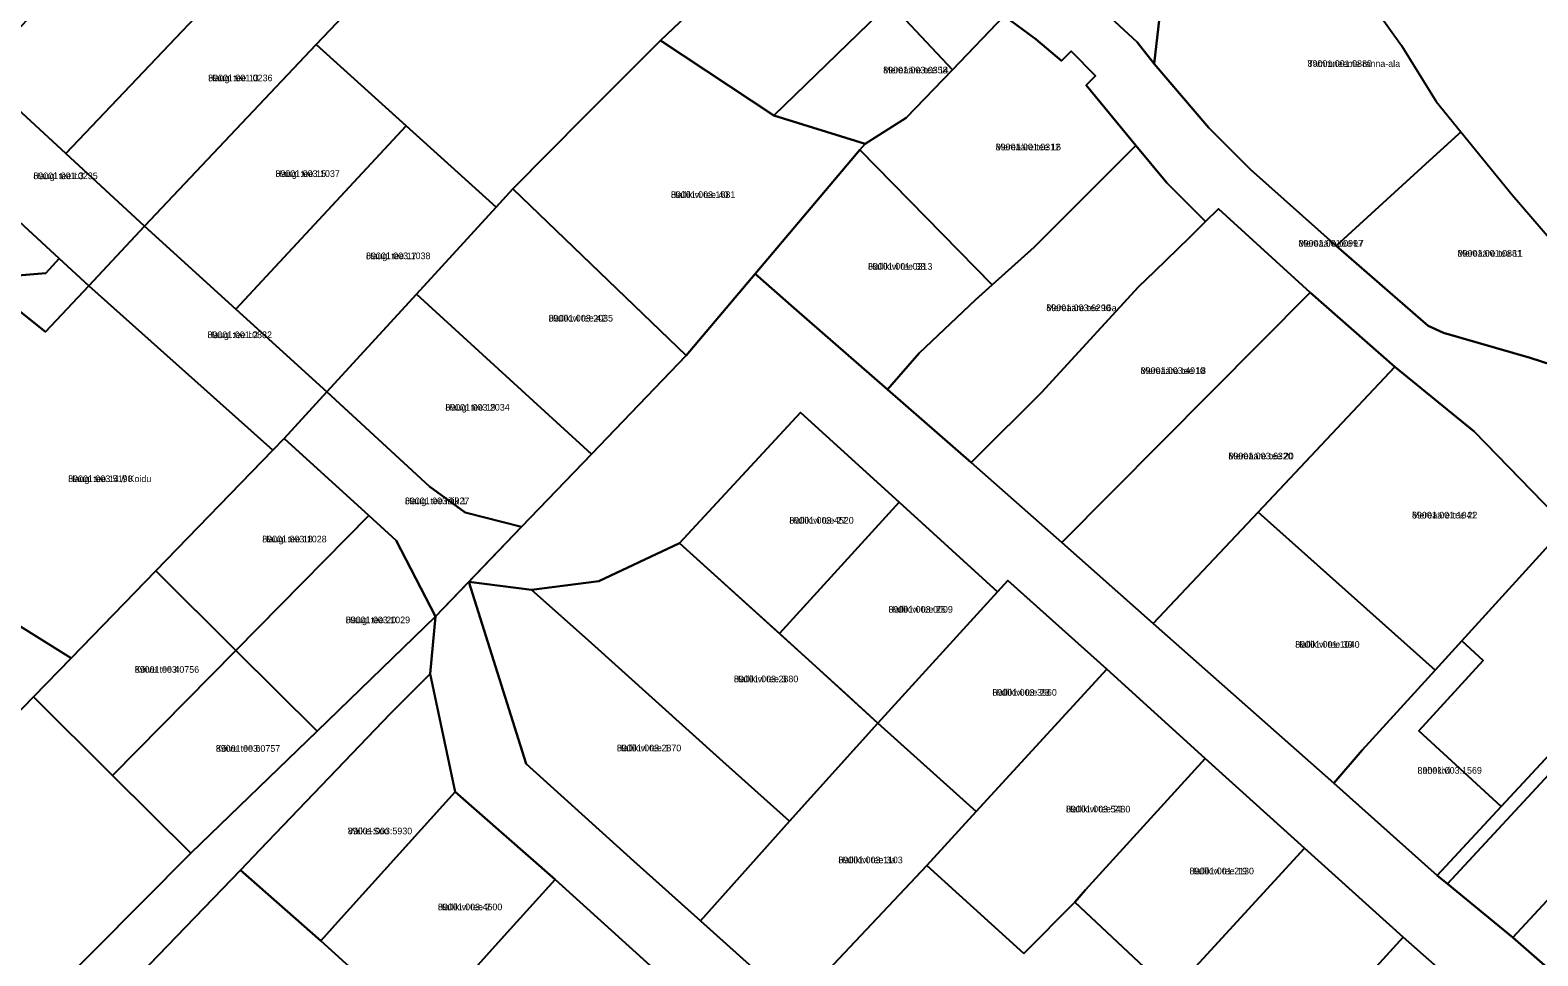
# Model space of a CAD drawing. Extents: x 526849 to 562296, y 6591741 to 6618546.
# Drawn here: x 550234.2 to 550573.7, y 6599209.9 to 6599418.5 of the extents above; entities that cross this region are included whole.
import ezdxf

# ---------------------------------------------------------------- set-up
doc = ezdxf.new("R2010")
doc.units = 0
for name, color, linetype in [('L_AADRESS', 7, 'Continuous'), ('PIIR', 7, 'Continuous'), ('TUNNUS', 7, 'Continuous')]:
    doc.layers.add(name, color=color, linetype=linetype)

msp = doc.modelspace()

# ---------------------------------------------------------------- linework, layer by layer
at = {"layer": 'PIIR'}
for points in [[(550338.48, 6599453.54), (550370.8, 6599421.44), (550391.08, 6599440.74), (550396.22, 6599451.02), (550407.35, 6599463.14), (550412.23, 6599460.02), (550417.73, 6599455.69), (550376.16, 6599416.14), (550359.05, 6599399.06), (550342.91, 6599382.73), (550339.12, 6599378.58), (550318.87, 6599396.92), (550298.56, 6599415.29), (550306.33, 6599423.38), (550319.47, 6599435.16), (550333.28, 6599447.47)], [(550376.16, 6599416.14), (550417.73, 6599455.69), (550419.39, 6599457.64), (550455.35, 6599423.66), (550453.51, 6599421.72), (550441.89, 6599409.52), (550427.82, 6599424.57), (550401.66, 6599399.22)], [(550263.02, 6599452.56), (550283, 6599433.66), (550242.17, 6599390.67), (550222.34, 6599408.94), (550243.43, 6599431.58)], [(550487.36, 6599410.9), (550489.63, 6599431.21), (550506.1, 6599445.17), (550515.6, 6599453.23), (550516.25, 6599453.78), (550522.47, 6599443.81), (550543.02, 6599415.02), (550550.88, 6599402.41), (550556.4, 6599395.59), (550555.84, 6599395.08), (550549.32, 6599389.11), (550528.35, 6599369.9), (550509.06, 6599387.08), (550499.62, 6599396.48)], [(550469.45, 6599428.95), (550464, 6599432.68), (550476.55, 6599445.78), (550480.91, 6599450.33), (550489.63, 6599431.21), (550487.36, 6599410.9), (550483.5, 6599415.75), (550475.54, 6599423.16)], [(550283, 6599433.66), (550289.09, 6599440.06), (550306.33, 6599423.38), (550298.56, 6599415.29), (550259.95, 6599374.33), (550242.17, 6599390.67)], [(550441.89, 6599409.52), (550431.44, 6599398.72), (550422.22, 6599392.9), (550401.66, 6599399.22), (550427.82, 6599424.57)], [(550441.89, 6599409.52), (550453.51, 6599421.72), (550460.67, 6599416.46), (550466.44, 6599411.56), (550468.6, 6599413.73), (550474.13, 6599408.17), (550472.01, 6599406.11), (550483.21, 6599392.49), (550460.29, 6599369.56), (550450.82, 6599361.08), (550421.04, 6599391.5), (550422.22, 6599392.9), (550431.44, 6599398.72)], [(550259.95, 6599374.33), (550298.56, 6599415.29), (550318.87, 6599396.92), (550280.5, 6599355.65)], [(550401.66, 6599399.22), (550422.22, 6599392.9), (550421.04, 6599391.5), (550397.45, 6599363.54), (550381.95, 6599345.17), (550342.91, 6599382.73), (550359.05, 6599399.06), (550376.16, 6599416.14)], [(550209.75, 6599395.56), (550222.34, 6599408.94), (550242.17, 6599390.67), (550259.95, 6599374.33), (550247.35, 6599360.87), (550240.73, 6599367)], [(550280.5, 6599355.65), (550318.87, 6599396.92), (550339.12, 6599378.58), (550321.17, 6599358.99), (550300.98, 6599336.96)], [(550189.25, 6599373.56), (550209.75, 6599395.56), (550240.73, 6599367), (550237.69, 6599363.71), (550227.81, 6599362.88), (550208.06, 6599340.59), (550181.7, 6599365.4)], [(550549.04, 6599351.83), (550528.35, 6599369.9), (550549.32, 6599389.11), (550555.84, 6599395.08), (550556.4, 6599395.59), (550567.95, 6599381.35), (550576.84, 6599371.11), (550590.97, 6599355.63), (550595.81, 6599351.02), (550596.43, 6599350.3), (550595.36, 6599349.21), (550590.01, 6599343.77), (550585.65, 6599339.33), (550579.2, 6599342.29), (550572.05, 6599344.67), (550552.5, 6599350.29)], [(550397.45, 6599363.54), (550421.04, 6599391.5), (550450.82, 6599361.08), (550447.1, 6599357.75), (550434.4, 6599345.67), (550427.23, 6599337.48), (550406.2, 6599355.88)], [(550446.09, 6599321.03), (550427.23, 6599337.48), (550434.4, 6599345.67), (550447.1, 6599357.75), (550450.82, 6599361.08), (550460.29, 6599369.56), (550483.21, 6599392.49), (550490.19, 6599384.06), (550498.86, 6599375.34), (550495.31, 6599371.79), (550487.37, 6599364.14), (550483.78, 6599360.68), (550461.95, 6599336.83), (550447.05, 6599322.05)], [(550342.91, 6599382.73), (550381.95, 6599345.17), (550360.57, 6599322.93), (550321.17, 6599358.99), (550339.12, 6599378.58)], [(550501.82, 6599378.23), (550522.44, 6599359.35), (550466.57, 6599303.05), (550446.09, 6599321.03), (550447.05, 6599322.05), (550461.95, 6599336.83), (550483.78, 6599360.68), (550487.37, 6599364.14), (550495.31, 6599371.79), (550498.86, 6599375.34)], [(550259.95, 6599374.33), (550280.5, 6599355.65), (550300.98, 6599336.96), (550291.38, 6599326.47), (550288.83, 6599323.85), (550247.35, 6599360.87)], [(550237.69, 6599363.71), (550240.73, 6599367), (550247.35, 6599360.87), (550237.63, 6599350.54), (550231.69, 6599355.25), (550210.88, 6599331.55), (550203.96, 6599323.72), (550203.55, 6599323.26), (550192.22, 6599310.51), (550196.62, 6599306.2), (550125.59, 6599231.83), (550116.88, 6599240.1), (550126.93, 6599250.64), (550129.93, 6599247.76), (550183.92, 6599304.66), (550183.9, 6599313.16), (550208.06, 6599340.59), (550227.81, 6599362.88)], [(550208.6, 6599318.8), (550203.96, 6599323.72), (550210.88, 6599331.55), (550231.69, 6599355.25), (550237.63, 6599350.54), (550247.35, 6599360.87), (550288.83, 6599323.85), (550262.46, 6599296.65), (550243.36, 6599276.95), (550196.62, 6599306.2)], [(550321.17, 6599358.99), (550360.57, 6599322.93), (550344.81, 6599306.54), (550332.11, 6599309.76), (550324.13, 6599315.66), (550300.98, 6599336.96)], [(550487.14, 6599284.76), (550466.57, 6599303.05), (550522.44, 6599359.35), (550541.54, 6599342.64), (550510.77, 6599309.88)], [(550510.77, 6599309.88), (550541.54, 6599342.64), (550559.43, 6599328.07), (550580.1, 6599306.74), (550556.65, 6599280.86), (550550.6, 6599274.25)], [(550300.98, 6599336.96), (550324.13, 6599315.66), (550332.11, 6599309.76), (550344.81, 6599306.54), (550332.95, 6599294.15), (550325.49, 6599286.38), (550316.63, 6599303.48), (550310.42, 6599309.14), (550291.38, 6599326.47)], [(550429.87, 6599312.11), (550402.92, 6599282.55), (550380.43, 6599302.85), (550407.7, 6599332.32)], [(550262.46, 6599296.65), (550288.83, 6599323.85), (550291.38, 6599326.47), (550310.42, 6599309.14), (550280.52, 6599278.71)], [(550580.1, 6599306.74), (550590.03, 6599318.17), (550614.16, 6599295.87), (550565.51, 6599243.53), (550546.92, 6599260.6), (550561.44, 6599276.48), (550556.65, 6599280.87)], [(550417.71, 6599269.08), (550402.92, 6599282.55), (550429.87, 6599312.11), (550452.04, 6599291.89), (550425.09, 6599262.33)], [(550280.52, 6599278.71), (550310.42, 6599309.14), (550316.63, 6599303.48), (550325.49, 6599286.38), (550298.78, 6599260.56)], [(550510.77, 6599309.88), (550550.6, 6599274.25), (550534.19, 6599256.27), (550527.77, 6599248.77), (550487.14, 6599284.76)], [(550098.07, 6599202.89), (550125.59, 6599231.83), (550196.62, 6599306.2), (550243.36, 6599276.95), (550234.92, 6599268.25), (550136.52, 6599166.45)], [(550390.15, 6599253.71), (550359.82, 6599281.04), (550347.11, 6599292.39), (550362.26, 6599294.34), (550380.43, 6599302.85), (550410.27, 6599275.81), (550425.09, 6599262.33), (550405.23, 6599240.22)], [(550262.46, 6599296.65), (550280.52, 6599278.71), (550252.74, 6599250.54), (550234.92, 6599268.25), (550243.36, 6599276.95)], [(550476.7, 6599274.49), (550447.25, 6599242.39), (550425.09, 6599262.33), (550454.4, 6599294.48)], [(550614.16, 6599295.87), (550616.14, 6599293.84), (550553.42, 6599226.1), (550551.1, 6599228), (550565.51, 6599243.53)], [(550347.11, 6599292.39), (550359.82, 6599281.04), (550390.15, 6599253.71), (550405.23, 6599240.22), (550385.14, 6599217.81), (550370.16, 6599231.26), (550345.87, 6599253.17), (550332.95, 6599294.15)], [(550616.14, 6599293.84), (550629.58, 6599280.38), (550568.13, 6599214.03), (550553.42, 6599226.1)], [(550270.33, 6599233.06), (550298.78, 6599260.56), (550325.49, 6599286.38), (550324.26, 6599273.48), (550315.22, 6599264.42), (550285.96, 6599233.86), (550281.52, 6599229.23), (550180.69, 6599124.74), (550171.48, 6599133.5)], [(550556.65, 6599280.86), (550561.44, 6599276.48), (550546.92, 6599260.6), (550565.51, 6599243.53), (550551.1, 6599228), (550527.77, 6599248.77), (550534.19, 6599256.27), (550550.6, 6599274.25)], [(550280.52, 6599278.71), (550298.78, 6599260.56), (550270.33, 6599233.06), (550252.74, 6599250.54)], [(550666.56, 6599242.67), (550663.17, 6599239.38), (550649.05, 6599226.15), (550606.23, 6599180.62), (550568.13, 6599214.03), (550629.58, 6599280.38)], [(550457.94, 6599210.41), (550436.13, 6599230.29), (550447.25, 6599242.39), (550476.7, 6599274.49), (550498.78, 6599254.37), (550471.9, 6599224.74), (550469.44, 6599222.01)], [(550299.6, 6599213.3), (550281.52, 6599229.23), (550285.96, 6599233.86), (550315.22, 6599264.42), (550324.26, 6599273.48), (550329.91, 6599246.82), (550303.46, 6599217.58)], [(550234.92, 6599268.25), (550252.74, 6599250.54), (550270.33, 6599233.06), (550171.48, 6599133.5), (550136.52, 6599166.45)], [(550425.09, 6599262.33), (550447.25, 6599242.39), (550436.13, 6599230.29), (550406.41, 6599198.7), (550385.14, 6599217.81), (550405.23, 6599240.22)], [(550469.44, 6599222.01), (550471.9, 6599224.74), (550498.78, 6599254.37), (550521.16, 6599234.18), (550494.13, 6599204.68), (550491.41, 6599201.71), (550486.27, 6599206.21)], [(550318.92, 6599195.8), (550299.6, 6599213.3), (550303.46, 6599217.58), (550329.91, 6599246.82), (550352.39, 6599227.08), (550340.92, 6599214.41), (550325.66, 6599197.45), (550321.81, 6599193.18)], [(550543.39, 6599214.09), (550513.92, 6599181.69), (550491.41, 6599201.71), (550494.13, 6599204.68), (550521.16, 6599234.18)], [(550457.94, 6599210.41), (550469.44, 6599222.01), (550486.27, 6599206.21), (550445.63, 6599162.62), (550406.41, 6599198.7), (550436.13, 6599230.29)], [(550180.69, 6599124.74), (550281.52, 6599229.23), (550299.6, 6599213.3), (550318.92, 6599195.8), (550321.81, 6599193.18), (550323.79, 6599191.39), (550324.38, 6599190.85), (550322.52, 6599188.93), (550222.08, 6599085.5)], [(550374.67, 6599206.97), (550347.76, 6599177.45), (550325.66, 6599197.45), (550340.92, 6599214.41), (550352.39, 6599227.08)], [(550513.92, 6599181.69), (550543.39, 6599214.09), (550557.54, 6599201.65), (550565.46, 6599194.05), (550548.07, 6599175.04), (550540.8, 6599166.48), (550536.04, 6599161.3)]]:
    msp.add_lwpolyline(points, close=True, dxfattribs=at)
for points in [[(550580.1, 6599306.74), (550559.43, 6599328.07), (550541.54, 6599342.64), (550522.44, 6599359.35), (550501.82, 6599378.23), (550498.86, 6599375.34), (550490.19, 6599384.06), (550483.21, 6599392.49), (550472.01, 6599406.11), (550474.13, 6599408.17), (550468.6, 6599413.73), (550466.44, 6599411.56), (550460.67, 6599416.46), (550453.51, 6599421.72)], [(550475.54, 6599423.16), (550483.5, 6599415.75), (550487.36, 6599410.9), (550499.62, 6599396.48), (550509.06, 6599387.08), (550528.35, 6599369.9), (550549.04, 6599351.83), (550552.5, 6599350.29), (550572.05, 6599344.67), (550579.2, 6599342.29)], [(550374.67, 6599206.97), (550352.39, 6599227.08), (550329.91, 6599246.82), (550324.26, 6599273.48), (550325.49, 6599286.38), (550344.81, 6599306.54), (550360.57, 6599322.93), (550381.95, 6599345.17), (550397.45, 6599363.54), (550406.2, 6599355.88), (550427.23, 6599337.48), (550446.09, 6599321.03), (550466.57, 6599303.05), (550487.14, 6599284.76), (550527.77, 6599248.77), (550551.1, 6599228), (550553.42, 6599226.1), (550568.13, 6599214.03), (550606.23, 6599180.65)], [(550557.54, 6599201.65), (550543.39, 6599214.09), (550521.16, 6599234.18), (550498.78, 6599254.37), (550476.7, 6599274.49), (550454.4, 6599294.48), (550452.04, 6599291.89), (550429.87, 6599312.11), (550407.7, 6599332.32), (550380.43, 6599302.85), (550362.26, 6599294.34), (550347.11, 6599292.39), (550332.95, 6599294.15), (550345.87, 6599253.17), (550370.16, 6599231.26), (550385.14, 6599217.81), (550406.41, 6599198.7)]]:
    msp.add_lwpolyline(points, dxfattribs=at)

# ---------------------------------------------------------------- texts
at = {"layer": 'L_AADRESS'}
for s, p in [('Mereääre tee 14', (550426.3, 6599408.74)), ('Tammneeme ranna-ala', (550521.88, 6599410.21)), ('Haugi tee 13', (550274.25, 6599406.97)), ('Mereääre tee 16', (550451.63, 6599391.4)), ('Haugi tee L3', (550234.88, 6599384.91)), ('Haugi tee 15', (550289.41, 6599385.41)), ('Hallikivi tee 40', (550378.48, 6599380.66)), ('Mereääre tee L7', (550519.85, 6599369.71)), ('Haugi tee 17', (550309.81, 6599366.88)), ('Hallikivi tee 38', (550422.87, 6599364.49)), ('Mereääre tee 11', (550555.66, 6599367.46)), ('Mereääre tee 16a', (550463.04, 6599355.17)), ('Hallikivi tee 42', (550350.94, 6599352.83)), ('Haugi tee L2', (550274.12, 6599349.09)), ('Mereääre tee 18', (550484.27, 6599341.01)), ('Haugi tee 19', (550327.68, 6599332.76)), ('Mereääre tee 20', (550504.05, 6599321.78)), ('Haugi tee 14 // Koidu', (550242.72, 6599316.65)), ('Haugi tee lõik 1', (550318.58, 6599311.67)), ('Hallikivi tee 27', (550405.15, 6599307.28)), ('Mereääre tee 22', (550545.41, 6599308.45)), ('Haugi tee 18', (550286.44, 6599303.06)), ('Hallikivi tee 25', (550427.48, 6599287.22)), ('Haugi tee 20', (550305.23, 6599284.85)), ('Hallikivi tee 30', (550519.1, 6599279.32)), ('Kõivu tee 4', (550257.72, 6599273.68)), ('Hallikivi tee 3', (550392.67, 6599271.54)), ('Hallikivi tee 23', (550450.9, 6599268.5)), ('Kõivu tee 6', (550275.98, 6599255.88)), ('Hallikivi tee 1', (550366.31, 6599255.98)), ('Lahekivi', (550546.64, 6599250.94)), ('Hallikivi tee 21', (550467.46, 6599242.21)), ('Väike-Soo', (550305.71, 6599237.28)), ('Hallikivi tee 3a', (550416.2, 6599230.76)), ('Hallikivi tee 19', (550495.3, 6599228.25)), ('Hallikivi tee 2', (550326, 6599220.16))]:
    msp.add_text(s, height=1.5, dxfattribs=at).set_placement(p)
at = {"layer": 'TUNNUS'}
for s, p in [('89001:003:0358', (550426.3, 6599408.74)), ('89001:001:0880', (550521.88, 6599410.21)), ('89001:001:0236', (550274.25, 6599406.97)), ('89001:001:0312', (550451.63, 6599391.4)), ('89001:001:0235', (550234.88, 6599384.91)), ('89001:003:1037', (550289.41, 6599385.41)), ('89001:003:1681', (550378.48, 6599380.66)), ('89001:001:0997', (550519.85, 6599369.71)), ('89001:001:0881', (550555.66, 6599367.46)), ('89001:003:1038', (550309.81, 6599366.88)), ('89001:001:0313', (550422.87, 6599364.49)), ('89001:003:6290', (550463.04, 6599355.17)), ('89001:003:2035', (550350.94, 6599352.83)), ('89001:001:0882', (550274.12, 6599349.09)), ('89001:003:4910', (550484.27, 6599341.01)), ('89001:003:2034', (550327.68, 6599332.76)), ('89001:003:6320', (550504.05, 6599321.78)), ('89001:003:5190', (550242.72, 6599316.65)), ('89001:003:1927', (550318.58, 6599311.67)), ('89001:003:4520', (550405.15, 6599307.28)), ('89001:001:1041', (550545.41, 6599308.45)), ('89001:003:1028', (550286.44, 6599303.06)), ('89001:003:0009', (550427.48, 6599287.22)), ('89001:003:1029', (550305.23, 6599284.85)), ('89001:001:1040', (550519.1, 6599279.32)), ('89001:003:0756', (550257.72, 6599273.68)), ('89001:003:2880', (550392.67, 6599271.54)), ('89001:003:3960', (550450.9, 6599268.5)), ('89001:003:0757', (550275.98, 6599255.88)), ('89001:003:2870', (550366.31, 6599255.98)), ('89001:003:1569', (550546.64, 6599250.94)), ('89001:003:5480', (550467.46, 6599242.21)), ('89001:003:5930', (550305.71, 6599237.28)), ('89001:003:1103', (550416.2, 6599230.76)), ('89001:001:2130', (550495.3, 6599228.25)), ('89001:003:4600', (550326, 6599220.16))]:
    msp.add_text(s, height=1.5, dxfattribs=at).set_placement(p)

doc.saveas('drawing.dxf')
